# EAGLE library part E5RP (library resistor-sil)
SIL RESISTOR
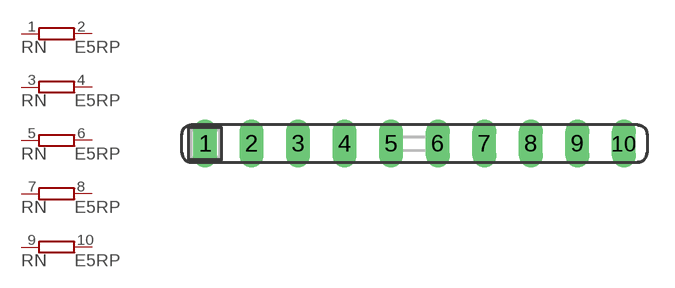
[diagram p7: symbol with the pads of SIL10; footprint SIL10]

Designator prefix RN; gates A=RPV B=RPV C=RPV D=RPV E=RPV

## E5RP (OC_FARNELL: unknown; OC_NEWARK: unknown)  [SIL10]
1  A:1  pas
2  A:2  pas
3  B:1  pas
4  B:2  pas
5  C:1  pas
6  C:2  pas
7  D:1  pas
8  D:2  pas
9  E:1  pas
10  E:2  pas

## Footprint SIL10 (pad centres in mm)
Single In Line
drill 0.813 long: 1 -11.43,0; 2 -8.89,0; 3 -6.35,0; 4 -3.81,0; 5 -1.27,0; 6 1.27,0; 7 3.81,0; 8 6.35,0; 9 8.89,0; 10 11.43,0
